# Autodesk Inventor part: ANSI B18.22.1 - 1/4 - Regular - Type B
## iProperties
Comments: To add or edit properties for Autodesk Inventor files, use iProperties.
Created: 2005-06
Part Number: ANSI B18.22.1 - 1/4 - Regular - Type B
Vendor: Autodesk Inc.
Document SubType Name: Modeling
Designer: John Blackburn
Material: Default
Description: Washer B
Standard: ANSI B18.22.1
Alert: To add or edit properties for Autodesk Inventor files, use iProperties.
Control State: 0
Master: False
Checked Out: False
Shininess: 64.0
Length Units: 11272
Angle Units: 11279
Time Units: 11290
Mass Units: 11286
Length Display Precision: 3
Angle Display Precision: 2
Compacted: True
Classification: un/spsc 31161807
Density: 0.0
Volumn: 0.0
Area: 0.0
PropertySet Name: Model Information
Author: John Blackburn
Revision Number: 8
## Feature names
1. Body [Extrusion]
